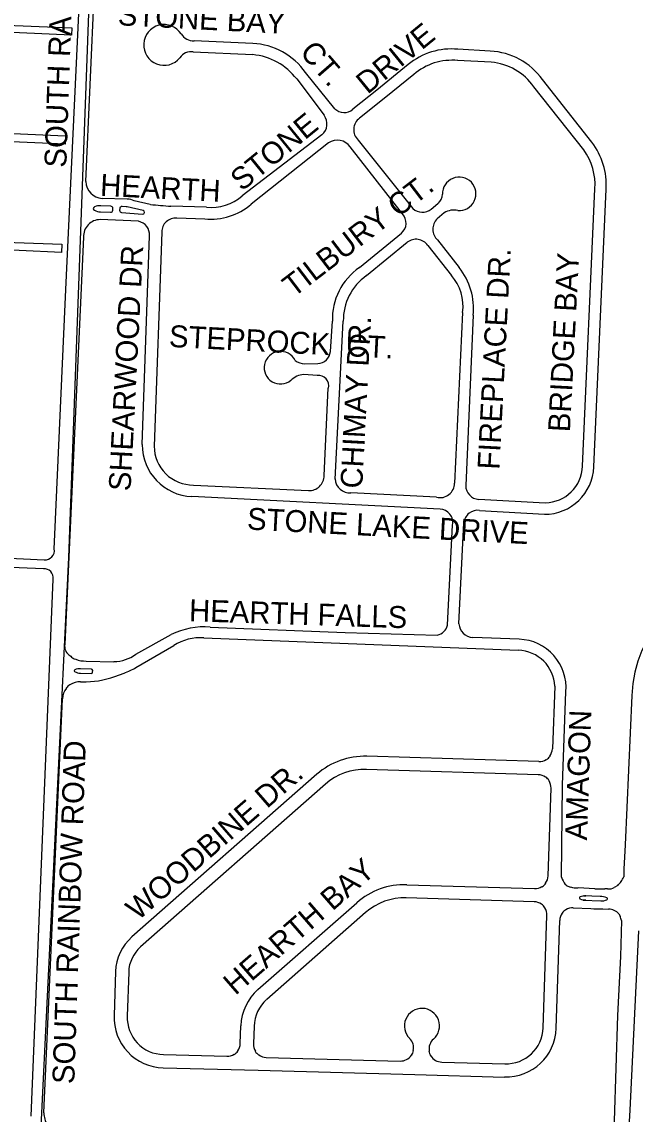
# Model space of a CAD drawing. Extents: x 0 to 712119, y 0 to 761125.
# Drawn here: x 661516 to 662915, y 716281 to 718772 of the extents above; entities that cross this region are included whole.
import ezdxf

# ---------------------------------------------------------------- set-up
doc = ezdxf.new("R2010")
doc.units = 0
for name, color, linetype in [('PAVED ROADS', 7, 'Continuous'), ('Priority 18', 7, 'Continuous'), ('street names', 7, 'Continuous')]:
    doc.layers.add(name, color=color, linetype=linetype)

msp = doc.modelspace()

# ---------------------------------------------------------------- linework, layer by layer
at = {"layer": 'PAVED ROADS'}
for points in [[(661589.7, 717570.1), (661616.1, 718161.5), (661649.7, 718872.2), (661655.5, 718878.2), (661659.4, 718896.6), (661662.7, 719001.3), (661667.4, 719114.3), (661671.6, 719238.1), (661673.3, 719324.1), (661676.7, 719468), (661682, 719625.1), (661685, 719712), (661688, 719732.4), (661692.3, 719823.1), (661695.7, 719877.5), (661698.4, 719906.4), (661701.3, 719964.2), (661699.5, 720027.4)], [(661661.4, 718408.3), (661681.5, 718849.5)], [(661443.4, 718766.2), (661629.7, 718758.2), (661629, 718742.1), (661442.1, 718749.9)], [(662042.6, 718723.1), (661908.9, 718729)], [(661906.9, 718703.6), (662042.6, 718697.4)], [(662584.6, 718705.3), (662510.7, 718709.7)], [(662397.3, 718674.6), (662325.3, 718616.1), (662271.1, 718572.9)], [(662586.6, 718680), (662510.1, 718683.9)], [(662142.8, 718641.9), (662205.3, 718559.1)], [(662229.6, 718574.1), (662163.2, 718656.4)], [(662409.8, 718652.1), (662346, 718600.3), (662286.3, 718552.4)], [(662816.4, 718497.7), (662703.7, 718640.6)], [(662797.7, 718480.3), (662684, 718624.2)], [(661426.1, 718520.4), (661615.4, 718511.9), (661614.8, 718493.6), (661422.6, 718502)], [(662200.3, 718514.4), (662018.5, 718375.4)], [(662215.5, 718496.3), (662038.8, 718356.3)], [(662283.1, 718502.7), (662407.7, 718346.6)], [(662384.3, 718334.3), (662264.8, 718486.9)], [(662795.3, 717758.9), (662823.2, 718391.5)], [(662821, 717757.5), (662848.7, 718390.4)], [(661756.1, 718367.9), (661699.2, 718369.6)], [(661718.5, 718351.9), (661695.6, 718352.8)], [(661723.1, 718342.7), (661723.3, 718346.7)], [(661739, 718346.6), (661738.7, 718342.7), (661738.7, 718342.7)], [(661754, 718350.5), (661744.3, 718351.2)], [(661792.2, 718341.8), (661755.8, 718350.2)], [(661808.8, 718355.9), (661772, 718364.1)], [(661937, 718349.3), (661855.9, 718351.7)], [(662449.6, 718345.1), (662465.2, 718357.7)], [(661781.8, 718317.4), (661694.6, 718321.3)], [(661695.1, 718338.8), (661718, 718337.9)], [(661743.3, 718337.3), (661791, 718333.9)], [(661933.1, 718322.6), (661869.3, 718324.5)], [(662479.5, 718336.8), (662463.3, 718323.1)], [(661834.8, 718292.9), (661817.5, 717804.4)], [(662286.1, 718211.8), (662381.8, 718290.1)], [(661413.3, 718272.1), (661606.9, 718265.3), (661606.2, 718246.2), (661412.5, 718255)], [(661656.3, 718281.2), (661613.7, 717352.9)], [(661790.3, 717808.1), (661807.2, 718284.5)], [(662302, 718193.5), (662395.1, 718269.7)], [(662463.9, 718274.8), (662513.6, 718211.9)], [(662441.9, 718262.5), (662495.8, 718194)], [(662521.3, 718109.1), (662503, 717720.4), (662503, 717720.4)], [(662545.3, 718103), (662528.4, 717715)], [(662219.6, 718020.7), (662224.4, 718089.6)], [(662230.3, 717729.7), (662249.1, 718089.4)], [(662161.4, 717992.4), (662191.1, 717992.9)], [(662189.6, 717965.9), (662159, 717968.1)], [(662205.3, 717737.5), (662215, 717936.7)], [(661907.4, 717716), (662169.9, 717703.4)], [(662461.8, 717688.2), (662266.4, 717697.9)], [(662470, 717660.7), (661903.6, 717689.5)], [(662558.1, 717683.4), (662710.1, 717675.7)], [(662560.3, 717658.1), (662708, 717649.2)], [(662487.1, 717396.2), (662498.5, 717625.1)], [(662512.9, 717399.7), (662524.4, 717629.5)], [(661472.1, 717550.3), (661566.8, 717545.6)], [(661564.8, 717524.7), (661472.6, 717528.8)], [(661537.1, 716276.8), (661587.1, 717501.6)], [(661587.1, 717501.6), (661587.1, 717501.6)], [(661775.9, 717330.1), (661856.3, 717374.8)], [(661945.7, 717392.1), (662253.5, 717379.6), (662463.5, 717373.6)], [(661776.1, 717299.8), (661862.6, 717350.4)], [(661930.7, 717367.7), (662648.5, 717339.3)], [(662650.8, 717364.3), (662544.4, 717368)], [(661622.8, 717328.7), (661627.3, 717325.5)], [(661635.3, 717319.9), (661638.6, 717318.6)], [(661674.4, 717296.3), (661649.7, 717297)], [(661662.5, 717314.6), (661725.9, 717313.2)], [(661649.4, 717287), (661674.1, 717286.3)], [(661677.2, 717289.2), (661677.3, 717293.2)], [(661727.5, 717279.3), (661749.1, 717287.1)], [(661617.2, 717252.4), (661616.8, 717252.7)], [(661625.2, 717260.6), (661625.5, 717260.2)], [(661649.7, 717267.4), (661653.1, 717267.3)], [(662732.1, 717257), (662726.2, 717114.5)], [(662747.3, 716821.7), (662749.2, 717032.5), (662757.1, 717244.4)], [(661565.7, 716284.1), (661608.5, 717228.7)], [(662907.8, 717236.2), (662892.3, 716895.6), (662889.3, 716839.7), (662889.3, 716822.6)], [(662695.3, 717085.5), (662303, 717097.5)], [(662720.5, 717097.9), (662720.9, 717097.6)], [(662712.5, 717089.7), (662712.2, 717090.1)], [(662189, 717056.5), (661766.8, 716685.4)], [(662694.1, 717055.5), (662302, 717067.5)], [(662711.1, 717050.3), (662710.8, 717049.9)], [(662208.8, 717034), (661786.6, 716662.8)], [(662716.5, 716824.7), (662723.2, 717024.5)], [(662718.6, 717041.5), (662719, 717041.8)], [(662393.8, 716804.6), (662685.6, 716795.7)], [(662702.5, 716800.3), (662702.8, 716799.9)], [(662711.2, 716807.8), (662710.8, 716808.1)], [(662759.3, 716802.4), (662755.7, 716805.4)], [(662767.9, 716799.8), (662767.7, 716799.4)], [(662823.4, 716795.2), (662784.7, 716797.2)], [(662875.2, 716802.6), (662867.5, 716798.1)], [(662684.4, 716765.7), (662392.9, 716774.6)], [(662835.4, 716777.9), (662797.1, 716779.3), (662802.5, 716779.1)], [(662852.1, 716795), (662845.8, 716794.9)], [(662054.5, 716565.5), (662279.9, 716763.6)], [(662701.4, 716760.4), (662701.1, 716760)], [(662708.9, 716751.7), (662709.3, 716752)], [(662756.7, 716747.7), (662757, 716747.3)], [(662774, 716752), (662813.8, 716750.5)], [(662796.8, 716769.3), (662836.7, 716767.8)], [(662802.2, 716769.1), (662796.8, 716769.3), (662796.8, 716769.3)], [(662841.2, 716749.3), (662854.5, 716748.9)], [(662883.7, 716722.8), (662883, 716695.3), (662881.8, 716641.1), (662874.9, 716506.2), (662867.5, 716266), (662864.7, 716245.5), (662860.9, 716229.5), (662850.4, 716211.7), (662834.8, 716197.4), (662816.3, 716188), (662787.3, 716180.7), (662767.1, 716178.2), (662743.6, 716177.7), (661610.7, 716232.7)], [(662299.7, 716741.1), (662074.3, 716542.9)], [(662705, 716478.2), (662713.5, 716734.7)], [(662734.9, 716477.2), (662743.1, 716723)], [(662748.8, 716739.6), (662748.4, 716739.9)], [(662877.9, 716737.9), (662880.6, 716732.9)], [(662922.6, 716699.4), (662903, 716290.5), (662901.7, 716264.8), (662897.2, 716230.5), (662891.3, 716207.5), (662888.1, 716190.8), (662884.5, 716183.2), (662884.5, 716169.7), (662887.2, 716134.9), (662889, 716116.9), (662890.8, 716094.8), (662890.7, 716014.8), (662888.5, 715956.5), (662873.9, 715643.5), (662872.6, 715575.4), (662873.9, 715549.5), (662880.1, 715531.2), (662886.8, 715522.2), (662906.1, 715507.1), (662933.3, 715503.5), (662943, 715503.5), (663698.8, 715469)], [(661729.5, 716606.5), (661726.1, 716506.1)], [(661759.5, 716605.5), (661756.1, 716505.1)], [(662014.1, 716442.3), (662015.5, 716483)], [(662045.5, 716482), (662044.1, 716441.9)], [(662008.8, 716425.4), (662008.4, 716425.7)], [(662048.6, 716425), (662048.2, 716424.7)], [(662409.5, 716426.2), (662409, 716426.3)], [(662445.1, 716425.3), (662444.6, 716425.3)], [(661838.7, 716417.2), (661983.3, 716413.3)], [(662000, 716417.8), (662000.3, 716417.4)], [(662056.2, 716416.2), (662056.5, 716416.6)], [(662073.3, 716410.9), (662378.8, 716402.6)], [(662404.5, 716415.8), (662405, 716415.5)], [(662448.5, 716414.4), (662449, 716414.6)], [(662473.9, 716400), (662617.7, 716396.1)], [(661837.9, 716387.3), (662055, 716381.4), (662412.4, 716371.7), (662616.9, 716366.1)]]:
    msp.add_lwpolyline(points, dxfattribs=at)
for centre, radius, start, end in [((661840.2, 718719.5), 46.5, 32.5861, 320.7014), ((661907.1, 718761.4), 32.5, 211.3099, 273.1301), ((662033.7, 718564.6), 158.8, 35.3617, 86.7918), ((661901.3, 718674.8), 29.4, 78.994, 148.6327), ((662029.3, 718555.1), 142.9, 37.3974, 84.6862), ((662495.7, 718557.3), 153.1, 84.3901, 129.9611), ((662577.4, 718550), 155.5, 35.6545, 87.3322), ((662497.1, 718551), 133.6, 84.399, 130.7864), ((662574.6, 718546.2), 134.4, 35.5008, 84.8734), ((662251.1, 718596.4), 30.9, 226.037, 310.5551), ((662179.2, 718539.4), 32.7, 310.3475, 37.0205), ((662305, 718526.3), 32.2, 125.5859, 227.0881), ((662235.4, 718466.5), 35.8, 34.7714, 123.7482), ((662690.8, 718401.4), 158.2, 356.0039, 37.4951), ((662690.1, 718401.3), 133.5, 355.7625, 36.2692), ((662513.6, 718380), 38.2, 265.4358, 181.6041), ((661701.5, 718409.6), 40.1, 181.901, 266.7417), ((661756.6, 718335.6), 32.3, 61.655, 90.9781), ((661947.8, 718455.6), 106.8, 264.1688, 311.4071), ((662442.6, 718381.6), 33, 313.3624, 355.3363), ((661682.9, 718346.3), 4.12, 107.2683, 246.6599), ((661695.3, 718367.4), 28.6, 240.6519, 269.5121), ((661693.2, 718327.2), 25.8, 84.666, 116.5291), ((661718.2, 718342.9), 5, 267.8129, 357.8129), ((661718.3, 718346.9), 5, 357.8129, 87.8129), ((661743.7, 718342.3), 5, 175.8602, 265.8602), ((661744, 718346.2), 5, 85.8602, 175.8602), ((661753.1, 718338.6), 12, 76.8743, 85.8602), ((661791.3, 718337.9), 4, 265.8602, 76.8743), ((661989.6, 720117.7), 1771.1, 264.1427, 265.6711), ((661945.7, 718466), 143.9, 264.9855, 310.325), ((662429.5, 718370.3), 32.2, 227.3091, 308.6242), ((662501.1, 718302.5), 40.5, 76.4559, 122.2041), ((661694.7, 718282.9), 38.4, 90.2368, 182.5368), ((661775.4, 718286.3), 31.8, 356.8217, 78.454), ((661866.5, 718293), 31.7, 84.7504, 180.178), ((662361.9, 718313.4), 30.6, 310.5503, 43.1454), ((662487.4, 718299.3), 33.9, 135.3343, 226.1762), ((662415, 718243.8), 32.7, 34.8852, 127.5372), ((662364.7, 718095.4), 140.4, 123.9932, 182.3689), ((662375.4, 718090.7), 126.3, 125.5288, 180.5943), ((662418, 718124.4), 104.4, 351.5532, 41.7924), ((662396.2, 718118.6), 150, 354.0232, 38.4829), ((662105.9, 717983.5), 37.2, 26.7447, 309.4357), ((662189.4, 718023.1), 30.3, 273.1443, 355.4686), ((662163, 718032.6), 40.2, 233.6197, 267.8166), ((662163.4, 717919.3), 49, 95.1701, 133.696), ((662192.3, 717942.6), 23.5, 345.4815, 96.6391), ((661908.8, 717807.9), 118.5, 179.9134, 267.4658), ((661906.6, 717805.1), 89.1, 180.4301, 270.473), ((662708.2, 717762.1), 112.9, 269.915, 357.6785), ((662708.9, 717762.1), 86.4, 270.7615, 357.8689), ((662171.5, 717737.2), 33.8, 267.248, 0.6465), ((662264.8, 717732.5), 34.6, 184.5581, 272.6194), ((662469.9, 717720.3), 33.1, 255.819, 0.2324), ((662560.2, 717715.1), 31.8, 180.3376, 266.2439), ((662469.4, 717631), 29.7, 348.5194, 88.8248), ((662555.5, 717627.4), 31.1, 81.1194, 176.0526), ((661568.9, 717566.6), 21.1, 264.3992, 9.6456), ((661567, 717504.5), 20.3, 351.769, 96.2693), ((663173.7, 717230.2), 266, 89.4116, 178.7163), ((662456.4, 717404.6), 31.8, 283.0167, 344.6357), ((662547.3, 717402.4), 34.5, 184.4799, 265.2182), ((661932.8, 717218.9), 173.7, 85.7392, 116.1319), ((661638, 717348.3), 24.7, 169.3422, 232.2552), ((661924.6, 717249.1), 118.8, 87.0388, 121.4441), ((662647, 717253.9), 110.5, 355.0605, 88.0266), ((661645, 717342.2), 24.3, 223.2677, 246.3771), ((661724, 717401.2), 88, 271.2096, 306.1479), ((662645.5, 717252.7), 86.7, 2.8582, 88.0042), ((661637.2, 717292.4), 2.12, 103.9612, 249.5157), ((661647.7, 717273.3), 23.8, 84.9738, 117.4144), ((661661.2, 717381.1), 66.5, 250.1208, 271.1009), ((661674.3, 717293.3), 3, 358.2505, 88.2505), ((661692.7, 717442.2), 165, 289.978, 300.3339), ((661649.4, 717313.6), 26.6, 240.8297, 270.0125), ((661659.2, 717467.3), 200, 268.2505, 289.978), ((661674.2, 717289.3), 3, 268.2505, 358.2505), ((661648.5, 717227.5), 40, 141.3973, 178.2347), ((661648.5, 717227.5), 40.5, 125.088, 141.3973), ((661648.5, 717227.5), 40, 88.2505, 125.088), ((662297.9, 716932.6), 165, 88.2505, 131.3179), ((662696.2, 717115.5), 30.5, 302.2192, 324.1215), ((662696.2, 717115.5), 30, 324.1215, 358.0901), ((662696.2, 717115.5), 30, 268.2505, 302.2192), ((662297.9, 716932.6), 135, 88.2505, 131.3179), ((662693.2, 717025.5), 30, 54.1215, 88.2505), ((662693.2, 717025.5), 30.5, 32.2192, 54.1215), ((662693.2, 717025.5), 30, 358.0901, 32.2192), ((662686.5, 716825.7), 30, 324.1215, 358.0901), ((662796.9, 716837), 51.9, 197.1271, 217.4134), ((662832.9, 716847.2), 61.5, 313.4735, 336.4424), ((662388.8, 716639.7), 165, 88.2505, 131.3179), ((662686.5, 716825.7), 30, 268.2505, 302.2192), ((662686.5, 716825.7), 30.5, 302.2192, 324.1215), ((662787.7, 716868), 71.5, 246.6049, 253.7083), ((662783.6, 716845), 47.8, 250.8445, 271.2846), ((662853.6, 716828.1), 33.2, 267.4122, 294.8993), ((662388.8, 716639.7), 135, 88.2505, 131.3179), ((662790, 716774.5), 2.12, 103.9612, 249.5157), ((662802.2, 716795.7), 26.6, 240.8297, 270.0125), ((662800.5, 716755.5), 23.8, 84.9738, 117.4144), ((662852.3, 718094.8), 1299.9, 268.7276, 269.7116), ((662837, 716750.4), 27.6, 60.4822, 93.3662), ((662849.9, 716772.4), 2.12, 286.9854, 72.5398), ((662683.5, 716735.7), 30, 54.1215, 88.2505), ((662683.5, 716735.7), 30.5, 32.2192, 54.1215), ((662683.5, 716735.7), 30, 358.0901, 32.2192), ((662773.1, 716722), 30.5, 122.5493, 144.0054), ((662773.1, 716722), 30, 88.2505, 122.5493), ((662841, 717059.8), 310.5, 264.9816, 270.042), ((662838.9, 716795.1), 27.4, 265.3037, 295.1185), ((662854.7, 716718.8), 30, 39.4828, 90.4435), ((662773.1, 716722), 30, 144.0054, 178.0901), ((661969, 716441), 957.1, 17.1228, 17.7547), ((661839.4, 716602.8), 110, 131.3179, 178.0605), ((661839.4, 716602.8), 80, 131.3179, 178.0605), ((662130.4, 716479.1), 115, 131.3179, 178.0605), ((662130.4, 716479.1), 85, 131.3179, 178.0605), ((662428.6, 716482.6), 40, 311.2505, 225.6464), ((661841, 716502.2), 115, 178.0605, 268.4448), ((661841, 716502.2), 85, 178.0605, 268.4448), ((662620, 716481.1), 115, 268.4448, 358.0901), ((662620, 716481.1), 85, 268.4448, 358.0901), ((662379.6, 716432.6), 30, 347.9949, 45.638), ((662474.7, 716430), 30, 131.2421, 188.8947), ((661984.1, 716443.3), 30.5, 301.9441, 324.028), ((661984.1, 716443.3), 30, 324.028, 358.0605), ((662074.1, 716440.9), 30, 178.0605, 211.9386), ((662074.1, 716440.9), 30.5, 211.9386, 234.0219), ((662379.6, 716432.6), 30.5, 326.0927, 347.9949), ((662474.7, 716430), 30.5, 188.8947, 210.797), ((661984.1, 716443.3), 30, 268.4448, 301.9441), ((662074.1, 716440.9), 30, 234.0219, 268.4448), ((662379.6, 716432.6), 30, 268.4448, 326.0927), ((662474.7, 716430), 30, 210.797, 268.4448), ((661628.6, 716287.5), 63, 183.0871, 209.0615)]:
    msp.add_arc(centre, radius, start, end, dxfattribs=at)
at = {"layer": 'Priority 18'}
msp.add_lwpolyline([(661697.4, 720091.7), (661670.9, 718874.5), (661622.1, 717551.1), (661558.5, 716237.1), (661495, 714923.1), (661434.7, 713608.9), (661373.4, 712274)], dxfattribs=at)

# ---------------------------------------------------------------- texts
at = {"layer": 'street names'}
for s, rotation, p in [('SOUTH RAINBOW ROAD', 88.0489, (661617, 718439.2)), ('STONE BAY', 357.0105, (661733.8, 718764.6)), ('DRIVE', 39.21, (662304.4, 718605.6)), ('CT.', 310.9784, (662147.7, 718701.9)), ('STONE', 39.21, (662017.6, 718384.3)), ('HEARTH', 357.0105, (661693.4, 718375.8)), ('TILBURY CT.', 37.3662, (662135.2, 718142.4)), ('SHEARWOOD DR', 87.0105, (661763.6, 717701.2)), ('FIREPLACE DR.', 87.0105, (662605.2, 717750.3)), ('BRIDGE BAY', 87.0105, (662766.2, 717835.8)), ('CHIMAY DR.', 87.0105, (662292.2, 717707.2)), ('STEPROCK  CT.', 357.0105, (661850.5, 718031.1)), ('STONE LAKE DRIVE', 357.0105, (662028.7, 717614.7)), ('HEARTH FALLS', 358.1374, (661896.6, 717405.5)), ('AMAGON', 88.0489, (662805.2, 716905.2)), ('SOUTH RAINBOW ROAD', 88.0489, (661635.2, 716349.4)), ('WOODBINE DR.', 40.9813, (661780.5, 716721.1)), ('HEARTH BAY', 40.9813, (662002.8, 716550.9))]:
    msp.add_text(s, height=50, rotation=rotation, dxfattribs=at).set_placement(p)

doc.saveas('drawing.dxf')
